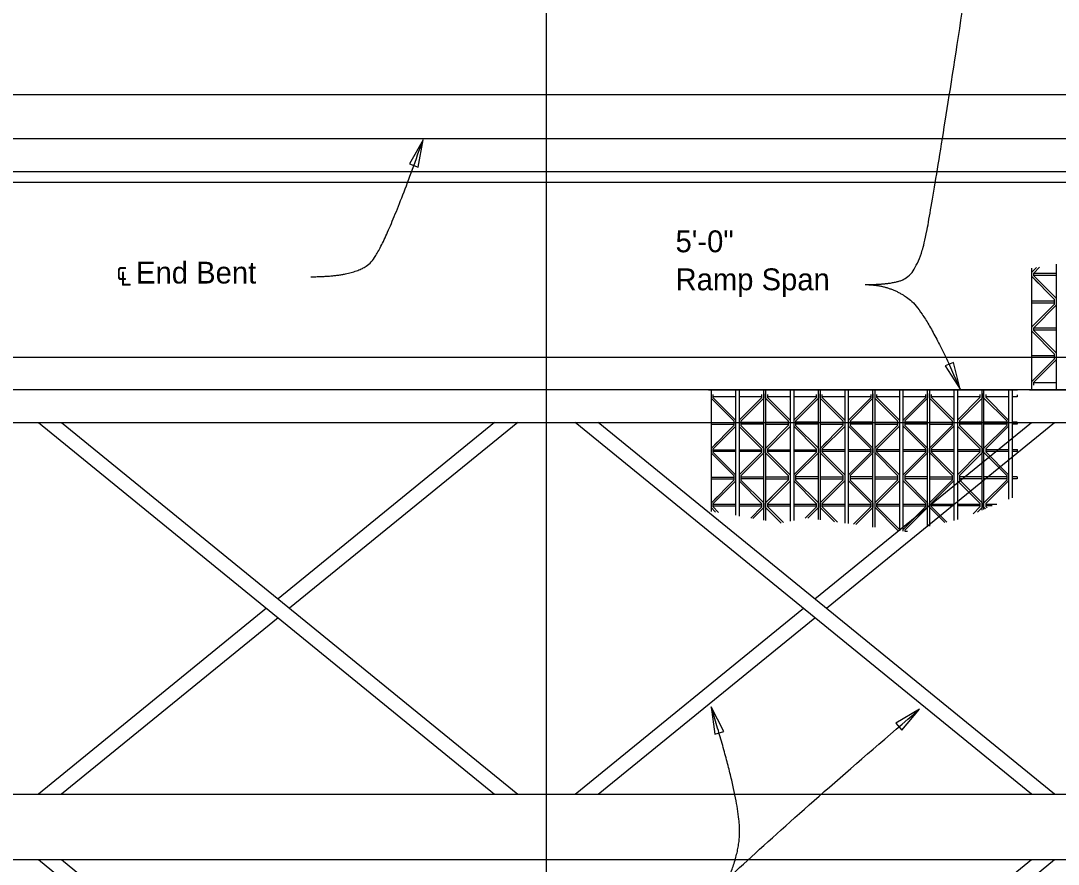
# Model space of a CAD drawing. Extents: x -58 to 62, y 0 to 81.
# Drawn here: x 24.75 to 36.63, y 19.83 to 29.48 of the extents above; entities that cross this region are included whole.
import ezdxf

# ---------------------------------------------------------------- set-up
doc = ezdxf.new("R2010")
doc.units = 0
for name, color, linetype in [('CL_Minor', 7, 'Continuous'), ('Dimension', 7, 'Continuous'), ('SteelMisc', 7, 'Continuous'), ('SteelMisc_h', 7, 'Continuous'), ('TextStructures', 7, 'Continuous'), ('Wood_h', 7, 'Continuous')]:
    doc.layers.add(name, color=color, linetype=linetype)

msp = doc.modelspace()

# ---------------------------------------------------------------- linework, layer by layer
at = {"layer": 'CL_Minor'}
for points in [[(30.77, 7.919), (30.77, 34.382), (30.77, 39.134)], [(14.012, 28.134), (47.505, 28.134)], [(15.607, 27.759), (45.02, 27.759), (45.933, 27.759)]]:
    msp.add_lwpolyline(points, dxfattribs=at)
at = {"layer": 'Dimension'}
for points in [[(29.357, 28.122), (29.204, 27.845), (29.303, 27.809)], [(35.505, 25.266), (35.431, 25.574), (35.334, 25.533)], [(32.656, 21.633), (32.698, 21.319), (32.799, 21.351)], [(35.042, 21.607), (34.77, 21.444), (34.839, 21.364)]]:
    msp.add_lwpolyline(points, close=True, dxfattribs=at)
for points in [[(28.072, 26.554), (28.591, 26.554), (28.917, 26.871), (29.357, 28.122)], [(32.625, 19.232), (32.982, 19.82), (32.982, 20.586), (32.656, 21.633)], [(33.619, 17.953), (31.74, 17.953), (31.538, 18.613), (35.042, 21.607)]]:
    msp.add_open_spline(points, degree=2, dxfattribs=at)
at = {"layer": 'SteelMisc'}
msp.add_line((42.77, 25.26), (18.77, 25.26), dxfattribs=at)
at = {"layer": 'SteelMisc_h'}
for p, q in [((36.328, 26.605), (36.381, 26.658)), ((36.328, 25.26), (36.328, 26.65)), ((36.415, 26.663), (36.348, 26.596)), ((36.609, 25.26), (36.609, 26.696)), ((36.328, 26.555), (36.404, 26.478)), ((36.588, 26.294), (36.328, 26.555)), ((36.348, 26.564), (36.348, 26.596)), ((36.609, 26.303), (36.348, 26.564)), ((36.608, 26.59), (36.35, 26.59)), ((36.35, 26.57), (36.609, 26.57)), ((36.329, 26.257), (36.587, 26.257)), ((36.332, 26.278), (36.589, 26.278)), ((36.588, 26.24), (36.588, 26.294)), ((36.328, 25.98), (36.588, 26.24)), ((36.61, 26.232), (36.348, 25.971)), ((36.328, 25.93), (36.404, 25.853)), ((36.588, 25.669), (36.328, 25.93)), ((36.348, 25.939), (36.348, 25.971)), ((36.609, 25.678), (36.348, 25.939)), ((36.608, 25.965), (36.35, 25.965)), ((36.35, 25.945), (36.609, 25.945)), ((36.588, 25.615), (36.588, 25.669)), ((18.312, 25.635), (43.228, 25.635)), ((36.328, 25.355), (36.588, 25.615)), ((36.329, 25.632), (36.587, 25.632)), ((36.332, 25.653), (36.589, 25.653)), ((36.61, 25.607), (36.348, 25.346)), ((36.348, 25.314), (36.348, 25.346)), ((36.608, 25.34), (36.35, 25.34)), ((32.625, 25.26), (36.164, 25.26)), ((32.654, 25.26), (32.654, 23.869)), ((32.674, 25.206), (32.674, 25.173)), ((32.935, 25.26), (32.935, 23.824)), ((32.976, 25.26), (32.976, 23.816)), ((33.237, 25.172), (33.237, 25.206)), ((33.258, 23.767), (33.258, 25.26)), ((33.258, 25.214), (33.258, 25.163)), ((33.279, 25.26), (33.279, 23.763)), ((33.299, 25.206), (33.299, 25.173)), ((33.56, 25.26), (33.56, 23.756)), ((33.601, 25.26), (33.601, 23.764)), ((33.862, 25.172), (33.862, 25.206)), ((33.883, 23.776), (33.883, 25.26)), ((33.883, 25.215), (33.883, 25.164)), ((33.904, 25.26), (33.904, 23.773)), ((33.924, 25.207), (33.924, 25.174)), ((34.185, 25.26), (34.185, 23.734)), ((34.226, 25.26), (34.226, 23.729)), ((34.487, 25.173), (34.487, 25.207)), ((34.508, 23.69), (34.508, 25.26)), ((34.508, 25.215), (34.508, 25.164)), ((34.529, 25.26), (34.529, 23.687)), ((34.549, 25.207), (34.549, 25.174)), ((34.81, 25.26), (34.81, 23.648)), ((34.851, 25.26), (34.851, 23.642)), ((35.112, 25.173), (35.112, 25.207)), ((35.133, 23.693), (35.133, 25.26)), ((35.133, 25.216), (35.133, 25.165)), ((35.154, 25.26), (35.154, 23.698)), ((35.174, 25.208), (35.174, 25.175)), ((35.435, 25.26), (35.435, 23.766)), ((35.476, 25.26), (35.476, 23.775)), ((35.737, 25.174), (35.737, 25.208)), ((35.758, 23.883), (35.758, 25.26)), ((35.758, 25.216), (35.758, 25.165)), ((35.779, 23.892), (35.779, 25.26)), ((35.779, 25.166), (35.779, 25.216)), ((35.799, 25.208), (35.799, 25.175)), ((36.06, 25.26), (36.06, 24.007)), ((36.101, 25.26), (36.101, 24.024)), ((36.159, 25.202), (36.159, 25.181)), ((36.299, 25.26), (39.838, 25.26)), ((32.654, 25.164), (32.914, 24.904)), ((32.936, 24.912), (32.674, 25.173)), ((32.934, 25.179), (32.676, 25.179)), ((33.234, 25.179), (32.975, 25.179)), ((32.977, 24.912), (33.237, 25.172)), ((32.997, 24.902), (33.258, 25.163)), ((33.258, 24.59), (33.258, 25.163)), ((33.279, 25.165), (33.539, 24.904)), ((33.561, 24.912), (33.299, 25.173)), ((33.559, 25.179), (33.301, 25.179)), ((33.859, 25.179), (33.6, 25.179)), ((33.602, 24.912), (33.862, 25.172)), ((33.622, 24.903), (33.883, 25.164)), ((33.883, 24.591), (33.883, 25.164)), ((33.904, 25.165), (34.164, 24.905)), ((34.186, 24.913), (33.924, 25.174)), ((34.184, 25.18), (33.926, 25.18)), ((34.484, 25.18), (34.225, 25.18)), ((34.227, 24.913), (34.487, 25.173)), ((34.247, 24.903), (34.508, 25.164)), ((34.508, 24.592), (34.508, 25.164)), ((34.529, 25.166), (34.789, 24.905)), ((34.811, 24.913), (34.549, 25.174)), ((34.809, 25.18), (34.551, 25.18)), ((35.109, 25.18), (34.85, 25.18)), ((34.852, 24.913), (35.112, 25.173)), ((34.872, 24.904), (35.133, 25.165)), ((35.133, 24.592), (35.133, 25.165)), ((35.154, 25.166), (35.414, 24.906)), ((35.436, 24.914), (35.174, 25.175)), ((35.434, 25.181), (35.176, 25.181)), ((35.734, 25.181), (35.475, 25.181)), ((35.477, 24.914), (35.737, 25.174)), ((35.497, 24.905), (35.758, 25.165)), ((35.758, 24.593), (35.758, 25.165)), ((36.039, 24.906), (35.779, 25.166)), ((36.06, 24.914), (35.799, 25.175)), ((36.062, 25.181), (35.8, 25.181)), ((36.159, 25.181), (36.101, 25.181)), ((18.312, 24.885), (43.228, 24.885)), ((24.953, 24.885), (30.177, 20.635)), ((25.217, 24.885), (30.441, 20.635)), ((30.177, 24.885), (27.697, 22.867)), ((30.441, 24.885), (27.829, 22.76)), ((36.323, 20.635), (31.099, 24.885)), ((36.587, 20.635), (31.363, 24.885)), ((32.914, 24.85), (32.654, 24.589)), ((32.655, 24.887), (32.913, 24.887)), ((32.658, 24.866), (32.915, 24.866)), ((32.935, 24.841), (32.674, 24.581)), ((32.914, 24.904), (32.914, 24.85)), ((32.977, 24.842), (33.237, 24.582)), ((32.997, 24.902), (32.997, 24.851)), ((33.258, 24.887), (32.997, 24.887)), ((32.997, 24.851), (33.258, 24.59)), ((33.256, 24.866), (32.998, 24.866)), ((33.539, 24.85), (33.279, 24.59)), ((33.28, 24.888), (33.538, 24.888)), ((33.283, 24.867), (33.54, 24.867)), ((33.56, 24.841), (33.299, 24.581)), ((33.539, 24.904), (33.539, 24.85)), ((33.602, 24.843), (33.862, 24.582)), ((33.622, 24.903), (33.622, 24.852)), ((33.883, 24.888), (33.622, 24.888)), ((33.622, 24.852), (33.883, 24.591)), ((33.881, 24.867), (33.623, 24.867)), ((33.843, 22.867), (36.323, 24.885)), ((34.164, 24.851), (33.904, 24.59)), ((33.905, 24.888), (34.163, 24.888)), ((33.908, 24.867), (34.165, 24.867)), ((34.185, 24.842), (33.924, 24.582)), ((33.975, 22.76), (36.587, 24.885)), ((34.164, 24.905), (34.164, 24.851)), ((34.227, 24.843), (34.487, 24.583)), ((34.247, 24.903), (34.247, 24.852)), ((34.508, 24.888), (34.247, 24.888)), ((34.247, 24.852), (34.508, 24.592)), ((34.506, 24.867), (34.248, 24.867)), ((34.789, 24.851), (34.529, 24.591)), ((34.53, 24.889), (34.788, 24.889)), ((34.533, 24.868), (34.79, 24.868)), ((34.81, 24.843), (34.549, 24.582)), ((34.789, 24.905), (34.789, 24.851)), ((34.852, 24.844), (35.112, 24.583)), ((34.872, 24.904), (34.872, 24.853)), ((35.133, 24.889), (34.872, 24.889)), ((34.872, 24.853), (35.133, 24.592)), ((35.131, 24.868), (34.873, 24.868)), ((35.414, 24.852), (35.154, 24.591)), ((35.155, 24.889), (35.413, 24.889)), ((35.158, 24.868), (35.415, 24.868)), ((35.435, 24.843), (35.174, 24.583)), ((35.414, 24.906), (35.414, 24.852)), ((35.477, 24.844), (35.737, 24.584)), ((35.497, 24.905), (35.497, 24.853)), ((35.758, 24.889), (35.497, 24.889)), ((35.497, 24.853), (35.758, 24.593)), ((35.756, 24.868), (35.498, 24.868)), ((36.039, 24.852), (35.779, 24.591)), ((36.035, 24.848), (35.779, 24.591)), ((36.038, 24.868), (35.782, 24.868)), ((36.037, 24.889), (35.783, 24.889)), ((36.061, 24.844), (35.799, 24.583)), ((36.039, 24.906), (36.039, 24.852)), ((36.159, 24.889), (36.101, 24.889)), ((36.159, 24.868), (36.102, 24.868)), ((36.159, 24.889), (36.159, 24.868)), ((32.654, 24.589), (32.73, 24.666)), ((33.258, 24.589), (33.258, 24.538)), ((33.279, 24.59), (33.355, 24.666)), ((33.883, 24.59), (33.883, 24.539)), ((33.904, 24.59), (33.98, 24.667)), ((34.508, 24.59), (34.508, 24.539)), ((34.529, 24.591), (34.605, 24.668)), ((35.133, 24.591), (35.133, 24.54)), ((35.154, 24.591), (35.23, 24.668)), ((35.758, 24.591), (35.758, 24.54)), ((35.779, 24.541), (35.779, 24.591)), ((32.654, 24.539), (32.914, 24.279)), ((32.674, 24.581), (32.674, 24.548)), ((32.936, 24.287), (32.674, 24.548)), ((32.676, 24.575), (32.935, 24.575)), ((32.934, 24.554), (32.676, 24.554)), ((33.234, 24.554), (32.975, 24.554)), ((32.977, 24.287), (33.237, 24.547)), ((32.978, 24.575), (33.238, 24.575)), ((32.997, 24.277), (33.258, 24.538)), ((33.237, 24.547), (33.237, 24.581)), ((33.258, 23.965), (33.258, 24.538)), ((33.279, 24.54), (33.539, 24.279)), ((33.299, 24.581), (33.299, 24.548)), ((33.561, 24.287), (33.299, 24.548)), ((33.301, 24.575), (33.56, 24.575)), ((33.559, 24.554), (33.301, 24.554)), ((33.859, 24.554), (33.6, 24.554)), ((33.602, 24.287), (33.862, 24.547)), ((33.603, 24.575), (33.863, 24.575)), ((33.622, 24.278), (33.883, 24.539)), ((33.862, 24.547), (33.862, 24.581)), ((33.883, 23.966), (33.883, 24.539)), ((33.904, 24.54), (34.164, 24.28)), ((33.924, 24.582), (33.924, 24.549)), ((34.186, 24.288), (33.924, 24.549)), ((33.926, 24.576), (34.185, 24.576)), ((34.184, 24.555), (33.926, 24.555)), ((34.484, 24.555), (34.225, 24.555)), ((34.227, 24.288), (34.487, 24.548)), ((34.228, 24.576), (34.488, 24.576)), ((34.247, 24.278), (34.508, 24.539)), ((34.487, 24.548), (34.487, 24.582)), ((34.508, 23.967), (34.508, 24.539)), ((34.529, 24.541), (34.789, 24.28)), ((34.549, 24.582), (34.549, 24.549)), ((34.811, 24.288), (34.549, 24.549)), ((34.551, 24.576), (34.81, 24.576)), ((34.809, 24.555), (34.551, 24.555)), ((35.109, 24.555), (34.85, 24.555)), ((34.852, 24.288), (35.112, 24.548)), ((34.853, 24.576), (35.113, 24.576)), ((34.872, 24.279), (35.133, 24.54)), ((35.112, 24.548), (35.112, 24.582)), ((35.133, 23.967), (35.133, 24.54)), ((35.154, 24.541), (35.414, 24.281)), ((35.174, 24.583), (35.174, 24.55)), ((35.436, 24.289), (35.174, 24.55)), ((35.176, 24.577), (35.435, 24.577)), ((35.434, 24.556), (35.176, 24.556)), ((35.734, 24.556), (35.475, 24.556)), ((35.477, 24.289), (35.737, 24.549)), ((35.478, 24.577), (35.738, 24.577)), ((35.497, 24.28), (35.758, 24.54)), ((35.737, 24.549), (35.737, 24.583)), ((35.758, 23.968), (35.758, 24.54)), ((36.039, 24.281), (35.779, 24.541)), ((35.799, 24.583), (35.799, 24.55)), ((36.06, 24.289), (35.799, 24.55)), ((36.062, 24.556), (35.8, 24.556)), ((35.802, 24.577), (36.062, 24.577)), ((36.101, 24.577), (36.164, 24.577)), ((36.159, 24.556), (36.101, 24.556)), ((36.159, 24.577), (36.159, 24.556)), ((32.655, 24.262), (32.913, 24.262)), ((32.658, 24.241), (32.915, 24.241)), ((32.914, 24.279), (32.914, 24.225)), ((32.997, 24.277), (32.997, 24.226)), ((33.258, 24.262), (32.997, 24.262)), ((33.256, 24.241), (32.998, 24.241)), ((33.28, 24.263), (33.538, 24.263)), ((33.283, 24.242), (33.54, 24.242)), ((33.539, 24.279), (33.539, 24.225)), ((33.622, 24.278), (33.622, 24.227)), ((33.883, 24.263), (33.622, 24.263)), ((33.881, 24.242), (33.623, 24.242)), ((33.905, 24.263), (34.163, 24.263)), ((33.908, 24.242), (34.165, 24.242)), ((34.164, 24.28), (34.164, 24.226)), ((34.247, 24.278), (34.247, 24.227)), ((34.508, 24.263), (34.247, 24.263)), ((34.506, 24.242), (34.248, 24.242)), ((34.53, 24.264), (34.788, 24.264)), ((34.533, 24.243), (34.79, 24.243)), ((34.789, 24.28), (34.789, 24.226)), ((34.872, 24.279), (34.872, 24.228)), ((35.133, 24.264), (34.872, 24.264)), ((35.131, 24.243), (34.873, 24.243)), ((35.155, 24.264), (35.413, 24.264)), ((35.158, 24.243), (35.415, 24.243)), ((35.414, 24.281), (35.414, 24.227)), ((35.497, 24.28), (35.497, 24.228)), ((35.758, 24.264), (35.497, 24.264)), ((35.756, 24.243), (35.498, 24.243)), ((36.038, 24.243), (35.782, 24.243)), ((36.037, 24.264), (35.783, 24.264)), ((36.039, 24.281), (36.039, 24.227)), ((36.159, 24.264), (36.101, 24.264)), ((36.159, 24.243), (36.102, 24.243)), ((36.159, 24.264), (36.159, 24.243)), ((32.914, 24.225), (32.654, 23.964)), ((32.935, 24.216), (32.674, 23.956)), ((32.977, 24.217), (33.237, 23.957)), ((32.997, 24.226), (33.258, 23.965)), ((33.539, 24.225), (33.279, 23.965)), ((33.56, 24.216), (33.299, 23.956)), ((33.602, 24.218), (33.862, 23.957)), ((33.622, 24.227), (33.883, 23.966)), ((34.164, 24.226), (33.904, 23.965)), ((34.185, 24.217), (33.924, 23.957)), ((34.227, 24.218), (34.487, 23.958)), ((34.247, 24.227), (34.508, 23.967)), ((34.789, 24.226), (34.529, 23.966)), ((34.81, 24.218), (34.549, 23.957)), ((34.852, 24.219), (35.112, 23.958)), ((34.872, 24.228), (35.133, 23.967)), ((35.414, 24.227), (35.154, 23.966)), ((35.435, 24.218), (35.174, 23.958)), ((35.477, 24.219), (35.737, 23.959)), ((35.497, 24.228), (35.758, 23.968)), ((36.039, 24.227), (35.779, 23.966)), ((36.035, 24.223), (35.779, 23.966)), ((36.061, 24.219), (35.799, 23.958)), ((32.654, 23.964), (32.73, 24.041)), ((33.279, 23.965), (33.355, 24.041)), ((33.904, 23.965), (33.98, 24.042)), ((34.529, 23.966), (34.605, 24.043)), ((35.154, 23.966), (35.23, 24.043)), ((32.654, 23.914), (32.707, 23.861)), ((32.674, 23.956), (32.674, 23.923)), ((32.741, 23.856), (32.674, 23.923)), ((32.676, 23.95), (32.935, 23.95)), ((32.934, 23.929), (32.676, 23.929)), ((33.234, 23.929), (32.975, 23.929)), ((32.978, 23.95), (33.238, 23.95)), ((33.108, 23.793), (33.237, 23.922)), ((33.133, 23.789), (33.258, 23.913)), ((33.237, 23.922), (33.237, 23.956)), ((33.258, 23.964), (33.258, 23.913)), ((33.279, 23.915), (33.459, 23.735)), ((33.299, 23.956), (33.299, 23.923)), ((33.483, 23.74), (33.299, 23.923)), ((33.301, 23.95), (33.56, 23.95)), ((33.559, 23.929), (33.301, 23.929)), ((33.859, 23.929), (33.6, 23.929)), ((33.603, 23.95), (33.863, 23.95)), ((33.73, 23.791), (33.862, 23.922)), ((33.762, 23.793), (33.883, 23.914)), ((33.862, 23.922), (33.862, 23.956)), ((33.883, 23.965), (33.883, 23.914)), ((33.904, 23.915), (34.068, 23.75)), ((33.924, 23.957), (33.924, 23.924)), ((34.103, 23.746), (33.924, 23.924)), ((33.926, 23.951), (34.185, 23.951)), ((34.184, 23.93), (33.926, 23.93)), ((34.484, 23.93), (34.225, 23.93)), ((34.228, 23.951), (34.488, 23.951)), ((34.285, 23.721), (34.487, 23.923)), ((34.311, 23.717), (34.508, 23.914)), ((34.487, 23.923), (34.487, 23.957)), ((34.508, 23.965), (34.508, 23.914)), ((34.529, 23.916), (34.789, 23.655)), ((34.549, 23.957), (34.549, 23.924)), ((34.811, 23.663), (34.549, 23.924)), ((34.551, 23.951), (34.81, 23.951)), ((34.809, 23.93), (34.551, 23.93)), ((35.109, 23.93), (34.85, 23.93)), ((34.852, 23.663), (35.112, 23.923)), ((34.853, 23.951), (35.113, 23.951)), ((34.872, 23.654), (35.133, 23.915)), ((35.112, 23.923), (35.112, 23.957)), ((35.133, 23.966), (35.133, 23.915)), ((35.154, 23.916), (35.329, 23.74)), ((35.174, 23.958), (35.174, 23.925)), ((35.353, 23.746), (35.174, 23.925)), ((35.176, 23.952), (35.435, 23.952)), ((35.434, 23.931), (35.176, 23.931)), ((35.734, 23.931), (35.475, 23.931)), ((35.478, 23.952), (35.738, 23.952)), ((35.654, 23.841), (35.737, 23.924)), ((35.704, 23.861), (35.758, 23.915)), ((35.737, 23.924), (35.737, 23.958)), ((35.758, 23.966), (35.758, 23.915)), ((35.758, 23.883), (35.758, 23.915)), ((35.779, 23.916), (35.779, 23.966)), ((35.796, 23.899), (35.779, 23.916)), ((35.799, 23.958), (35.799, 23.925)), ((35.817, 23.908), (35.799, 23.925)), ((35.874, 23.931), (35.8, 23.931)), ((35.802, 23.952), (35.925, 23.952)), ((34.789, 23.655), (34.789, 23.651)), ((34.872, 23.654), (34.872, 23.639)), ((34.905, 23.639), (34.875, 23.639)), ((27.565, 22.76), (24.953, 20.635)), ((31.099, 20.635), (33.711, 22.76)), ((27.697, 22.652), (25.217, 20.635)), ((31.363, 20.635), (33.843, 22.652)), ((18.312, 20.635), (43.228, 20.635)), ((18.312, 19.885), (43.228, 19.885)), ((24.953, 19.885), (30.177, 15.635)), ((25.217, 19.885), (30.441, 15.635)), ((34.205, 18.162), (36.323, 19.885)), ((34.584, 18.255), (36.587, 19.885))]:
    msp.add_line(p, q, dxfattribs=at)
at = {"layer": 'TextStructures'}
for points in [[(34.419, 26.464), (34.802, 26.464), (35.01, 26.64), (35.162, 27.159), (35.633, 30.258)], [(34.419, 26.464), (34.698, 26.464), (35.13, 26.145), (35.505, 25.266)]]:
    msp.add_open_spline(points, degree=2, dxfattribs=at)
at = {"layer": 'Wood_h'}
for p, q in [((42.575, 28.634), (18.933, 28.634)), ((42.575, 27.634), (18.933, 27.634))]:
    msp.add_line(p, q, dxfattribs=at)

# ---------------------------------------------------------------- texts
at = {"layer": 'Dimension'}
for s, p in [('5\'-0" ', (32.248, 26.834)), ('Ramp Span', (32.248, 26.399))]:
    msp.add_text(s, height=0.25, dxfattribs=at).set_placement(p)
at = {"layer": 'TextStructures'}
msp.add_text('℄ End Bent', height=0.25, dxfattribs=at).set_placement((25.843, 26.476))

doc.saveas('drawing.dxf')
